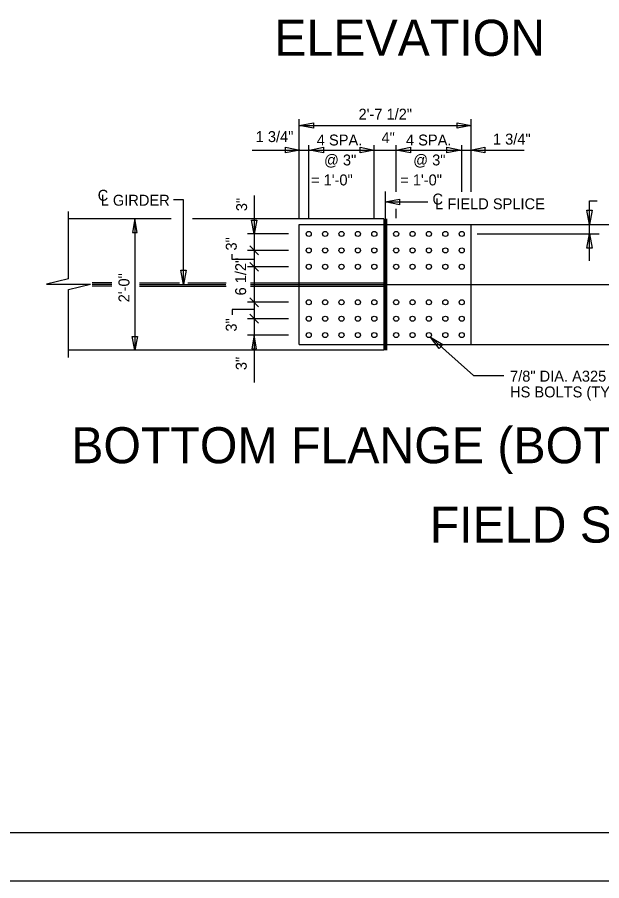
# Model space of a CAD drawing. Extents: x 1970675.2 to 1970715, y 796143 to 796167.2.
# Drawn here: x 1970692.92 to 1970699.6, y 796143.05 to 796152.92 of the extents above; entities that cross this region are included whole.
import ezdxf

# ---------------------------------------------------------------- set-up
doc = ezdxf.new("R2010")
doc.units = 0
for name, color, linetype in [('BR_AUTO DIMENSION', 7, 'Continuous'), ('BR_BORDER LINES', 7, 'Continuous'), ('BR_CENTER LINES', 7, 'Continuous'), ('BR_STRUCTURAL STEEL', 7, 'Continuous'), ('BR_TEXT', 7, 'Continuous'), ('Default', 7, 'Continuous'), ('Level 31', 7, 'Continuous')]:
    doc.layers.add(name, color=color, linetype=linetype)

msp = doc.modelspace()

# ---------------------------------------------------------------- linework, layer by layer
at = {"layer": 'BR_AUTO DIMENSION'}
for p, q in [((1970696.1441, 796150.6217), (1970696.1441, 796151.7541)), ((1970698.1128, 796150.9227), (1970698.1128, 796151.7523)), ((1970696.1441, 796151.6811), (1970698.1128, 796151.6811)), ((1970696.2535, 796150.6217), (1970696.2535, 796151.4572)), ((1970697.0035, 796150.6217), (1970697.0035, 796151.4572)), ((1970697.2535, 796150.9246), (1970697.2535, 796151.4572)), ((1970698.0035, 796150.9246), (1970698.0035, 796151.4572)), ((1970695.6086, 796151.401), (1970698.7162, 796151.401)), ((1970695.6291, 796150.8829), (1970695.6291, 796148.7417)), ((1970694.8216, 796150.8328), (1970694.7057, 796150.8328)), ((1970694.8216, 796149.8631), (1970694.8216, 796150.8328)), ((1970699.4636, 796150.1353), (1970699.4636, 796150.822)), ((1970699.4636, 796150.822), (1970699.5511, 796150.822)), ((1970697.2535, 796150.6217), (1970697.2535, 796150.7292)), ((1970694.2638, 796150.6131), (1970694.2638, 796149.1131)), ((1970698.1801, 796150.5506), (1970699.5735, 796150.5506)), ((1970696.022, 796150.4412), (1970695.5534, 796150.4412)), ((1970698.1801, 796150.4412), (1970699.5735, 796150.4412)), ((1970695.6788, 796150.2032), (1970695.5794, 796150.3042)), ((1970696.022, 796150.2537), (1970695.5534, 796150.2537)), ((1970696.022, 796150.0662), (1970695.5534, 796150.0662)), ((1970695.6788, 796150.0157), (1970695.5794, 796150.1167)), ((1970695.6788, 796149.6094), (1970695.5794, 796149.7105)), ((1970696.022, 796149.66), (1970695.5534, 796149.66)), ((1970696.022, 796149.4725), (1970695.5534, 796149.4725)), ((1970695.6788, 796149.4219), (1970695.5794, 796149.523)), ((1970696.022, 796149.285), (1970695.5534, 796149.285)), ((1970698.1378, 796148.8218), (1970697.6466, 796149.2619)), ((1970698.1378, 796148.8218), (1970698.486, 796148.8218))]:
    msp.add_line(p, q, dxfattribs=at)
for points in [[(1970696.3066, 796151.6498), (1970696.1441, 796151.6811), (1970696.3066, 796151.7123)], [(1970697.9503, 796151.7123), (1970698.1128, 796151.6811), (1970697.9503, 796151.6498)], [(1970695.9894, 796151.4322), (1970696.1519, 796151.401), (1970695.9894, 796151.3697)], [(1970696.4238, 796151.3697), (1970696.2613, 796151.401), (1970696.4238, 796151.4322)], [(1970696.841, 796151.4322), (1970697.0035, 796151.401), (1970696.841, 796151.3697)], [(1970697.416, 796151.3697), (1970697.2535, 796151.401), (1970697.416, 796151.4322)], [(1970697.8331, 796151.4322), (1970697.9956, 796151.401), (1970697.8331, 796151.3697)], [(1970698.2675, 796151.3697), (1970698.105, 796151.401), (1970698.2675, 796151.4322)], [(1970697.291, 796150.7756), (1970697.1285, 796150.8069), (1970697.291, 796150.8381)], [(1970699.4949, 796150.7131), (1970699.4636, 796150.5506), (1970699.4324, 796150.7131)], [(1970694.2377, 796150.4568), (1970694.2898, 796150.4568), (1970694.2638, 796150.6131)], [(1970695.6591, 796150.5972), (1970695.6291, 796150.4412), (1970695.5991, 796150.5972)], [(1970699.4324, 796150.2787), (1970699.4636, 796150.4412), (1970699.4949, 796150.2787)], [(1970694.8529, 796150.0256), (1970694.8216, 796149.8631), (1970694.7904, 796150.0256)], [(1970695.6031, 796149.1287), (1970695.6552, 796149.1287), (1970695.6291, 796149.285)], [(1970694.2938, 796149.2691), (1970694.2638, 796149.1131), (1970694.2338, 796149.2691)], [(1970697.7468, 796149.1302), (1970697.6466, 796149.2619), (1970697.7885, 796149.1768)]]:
    msp.add_lwpolyline(points, close=True, dxfattribs=at)
for points in [[(1970697.1285, 796150.8069), (1970697.6142, 796150.8069)], [(1970695.6291, 796150.1477), (1970695.3762, 796150.1477), (1970695.3762, 796150.209)], [(1970695.6291, 796149.5785), (1970695.3762, 796149.5785), (1970695.3762, 796149.5172)]]:
    msp.add_lwpolyline(points, dxfattribs=at)
at = {"layer": 'BR_BORDER LINES'}
msp.add_line((1970677.2531, 796143.5963), (1970714.2857, 796143.5963), dxfattribs=at)
at = {"layer": 'BR_CENTER LINES'}
for p, q in [((1970697.1285, 796150.9272), (1970697.1285, 796149.1131)), ((1970694.0011, 796149.8631), (1970693.7767, 796149.8631)), ((1970694.3174, 796149.8631), (1970694.8216, 796149.8631)), ((1970694.8216, 796149.8631), (1970695.3067, 796149.8631)), ((1970695.5874, 796149.8631), (1970699.9325, 796149.8631))]:
    msp.add_line(p, q, dxfattribs=at)
at = {"layer": 'BR_STRUCTURAL STEEL'}
for p, q in [((1970694.682, 796150.6131), (1970693.5058, 796150.6131)), ((1970697.1129, 796150.6131), (1970694.9236, 796150.6131)), ((1970697.1129, 796150.6131), (1970697.1129, 796150.5506)), ((1970697.1441, 796150.6131), (1970697.1441, 796150.5506)), ((1970696.1441, 796149.1756), (1970696.1441, 796150.5506)), ((1970696.1441, 796150.5506), (1970698.1128, 796150.5506)), ((1970697.1129, 796150.5506), (1970697.1129, 796149.1756)), ((1970697.1441, 796150.5506), (1970697.1441, 796149.1756)), ((1970697.1441, 796150.5506), (1970701.0582, 796150.5506)), ((1970698.1128, 796149.1756), (1970698.1128, 796150.5506)), ((1970694.0011, 796149.8826), (1970693.7767, 796149.8826)), ((1970694.3174, 796149.8826), (1970694.7765, 796149.8826)), ((1970694.8715, 796149.8826), (1970695.3076, 796149.8826)), ((1970695.5883, 796149.8826), (1970697.1129, 796149.8826)), ((1970694.0011, 796149.8435), (1970693.7767, 796149.8435)), ((1970694.3174, 796149.8435), (1970695.3076, 796149.8435)), ((1970695.5883, 796149.8435), (1970697.1129, 796149.8435)), ((1970696.1441, 796149.1756), (1970698.1128, 796149.1756)), ((1970697.1129, 796149.1756), (1970697.1129, 796149.1131)), ((1970697.1441, 796149.1756), (1970697.1441, 796149.1131)), ((1970697.1441, 796149.1756), (1970701.0582, 796149.1756)), ((1970697.1129, 796149.1131), (1970693.5058, 796149.1131))]:
    msp.add_line(p, q, dxfattribs=at)
for centre in [(1970696.2535, 796150.4412), (1970696.2535, 796150.4412), (1970696.441, 796150.4412), (1970696.441, 796150.4412), (1970696.6285, 796150.4412), (1970696.6285, 796150.4412), (1970696.816, 796150.4412), (1970696.816, 796150.4412), (1970697.0035, 796150.4412), (1970697.0035, 796150.4412), (1970697.2535, 796150.4412), (1970697.2535, 796150.4412), (1970697.441, 796150.4412), (1970697.441, 796150.4412), (1970697.6285, 796150.4412), (1970697.6285, 796150.4412), (1970697.816, 796150.4412), (1970697.816, 796150.4412), (1970698.0035, 796150.4412), (1970698.0035, 796150.4412), (1970696.2535, 796150.2537), (1970696.2535, 796150.2537), (1970696.441, 796150.2537), (1970696.441, 796150.2537), (1970696.6285, 796150.2537), (1970696.6285, 796150.2537), (1970696.816, 796150.2537), (1970696.816, 796150.2537), (1970697.0035, 796150.2537), (1970697.0035, 796150.2537), (1970697.2535, 796150.2537), (1970697.2535, 796150.2537), (1970697.441, 796150.2537), (1970697.441, 796150.2537), (1970697.6285, 796150.2537), (1970697.6285, 796150.2537), (1970697.816, 796150.2537), (1970697.816, 796150.2537), (1970698.0035, 796150.2537), (1970698.0035, 796150.2537), (1970696.2535, 796150.0662), (1970696.2535, 796150.0662), (1970696.441, 796150.0662), (1970696.441, 796150.0662), (1970696.6285, 796150.0662), (1970696.6285, 796150.0662), (1970696.816, 796150.0662), (1970696.816, 796150.0662), (1970697.0035, 796150.0662), (1970697.0035, 796150.0662), (1970697.2535, 796150.0662), (1970697.2535, 796150.0662), (1970697.441, 796150.0662), (1970697.441, 796150.0662), (1970697.6285, 796150.0662), (1970697.6285, 796150.0662), (1970697.816, 796150.0662), (1970697.816, 796150.0662), (1970698.0035, 796150.0662), (1970698.0035, 796150.0662), (1970696.2535, 796149.66), (1970696.2535, 796149.66), (1970696.441, 796149.66), (1970696.441, 796149.66), (1970696.6285, 796149.66), (1970696.6285, 796149.66), (1970696.816, 796149.66), (1970696.816, 796149.66), (1970697.0035, 796149.66), (1970697.0035, 796149.66), (1970697.2535, 796149.66), (1970697.2535, 796149.66), (1970697.441, 796149.66), (1970697.441, 796149.66), (1970697.6285, 796149.66), (1970697.6285, 796149.66), (1970697.816, 796149.66), (1970697.816, 796149.66), (1970698.0035, 796149.66), (1970698.0035, 796149.66), (1970696.2535, 796149.4725), (1970696.2535, 796149.4725), (1970696.441, 796149.4725), (1970696.441, 796149.4725), (1970696.6285, 796149.4725), (1970696.6285, 796149.4725), (1970696.816, 796149.4725), (1970696.816, 796149.4725), (1970697.0035, 796149.4725), (1970697.0035, 796149.4725), (1970697.2535, 796149.4725), (1970697.2535, 796149.4725), (1970697.441, 796149.4725), (1970697.441, 796149.4725), (1970697.6285, 796149.4725), (1970697.6285, 796149.4725), (1970697.816, 796149.4725), (1970697.816, 796149.4725), (1970698.0035, 796149.4725), (1970698.0035, 796149.4725), (1970696.2535, 796149.285), (1970696.2535, 796149.285), (1970696.441, 796149.285), (1970696.441, 796149.285), (1970696.6285, 796149.285), (1970696.6285, 796149.285), (1970696.816, 796149.285), (1970696.816, 796149.285), (1970697.0035, 796149.285), (1970697.0035, 796149.285), (1970697.2535, 796149.285), (1970697.2535, 796149.285), (1970697.441, 796149.285), (1970697.441, 796149.285), (1970697.6285, 796149.285), (1970697.6285, 796149.285), (1970697.816, 796149.285), (1970697.816, 796149.285), (1970698.0035, 796149.285), (1970698.0035, 796149.285)]:
    msp.add_circle(centre, 0.0293, dxfattribs=at)
at = {"layer": 'Default'}
for p, q in [((1970693.5058, 796149.9288), (1970693.5058, 796150.6964)), ((1970693.5058, 796149.9288), (1970693.254, 796149.8684)), ((1970693.254, 796149.8684), (1970693.7576, 796149.8684)), ((1970693.5058, 796149.8079), (1970693.7576, 796149.8684)), ((1970693.5058, 796149.0297), (1970693.5058, 796149.8079))]:
    msp.add_line(p, q, dxfattribs=at)
at = {"layer": 'Level 31'}
msp.add_lwpolyline([(1970675.2365, 796167.2463), (1970675.2365, 796143.0464), (1970714.8364, 796143.0464), (1970714.8364, 796167.2463)], dxfattribs=at)

# ---------------------------------------------------------------- texts
at = {"layer": 'BR_TEXT'}
for s, height, p in [('ELEVATION', 0.4125, (1970695.8601, 796152.478)), ('2\'-7 1/2"', 0.125, (1970696.823, 796151.7481)), ('1 3/4"', 0.125, (1970695.6471, 796151.4919)), ('4 SPA. ', 0.125, (1970696.3457, 796151.453)), ('4"', 0.125, (1970697.0858, 796151.4796)), ('4 SPA. ', 0.125, (1970697.3657, 796151.453)), ('1 3/4"', 0.125, (1970698.3602, 796151.4635)), ('@ 3" ', 0.125, (1970696.4287, 796151.2248)), ('@ 3" ', 0.125, (1970697.4488, 796151.2248)), ('= 1\'-0"', 0.125, (1970696.2799, 796150.9967)), ('= 1\'-0"', 0.125, (1970697.3, 796150.9967)), ('C', 0.125, (1970693.8403, 796150.8211)), ('L GIRDER', 0.125, (1970693.8744, 796150.7645)), ('C', 0.125, (1970697.6684, 796150.7778)), ('L FIELD SPLICE', 0.125, (1970697.6996, 796150.7234)), ('7/8" DIA. A325', 0.125, (1970698.5558, 796148.7528)), ('HS BOLTS (TYP.)', 0.125, (1970698.5558, 796148.5727)), ('BOTTOM FLANGE (BOTTOM PL)', 0.4125, (1970693.5378, 796147.8194)), ('FIELD SPLICE DETAIL (TYPE 2)', 0.4125, (1970697.6374, 796146.912))]:
    msp.add_text(s, height=height, dxfattribs=at).set_placement(p)
for s, p in [('3"', (1970695.5488, 796150.7017)), ('3"', (1970695.4303, 796150.2515)), ('6 1/2"', (1970695.5377, 796149.7384)), ('2\'-0"', (1970694.2032, 796149.6596)), ('3"', (1970695.4303, 796149.3247)), ('3"', (1970695.5447, 796148.8843))]:
    msp.add_text(s, height=0.125, rotation=90, dxfattribs=at).set_placement(p)

doc.saveas('drawing.dxf')
